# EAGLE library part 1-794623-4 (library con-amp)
MICRO MATE N LOK Dual Row, grid 1.5 mm Source: http://catalog.tycoelectronics.com .. ENG_CD_794623_F.pdf
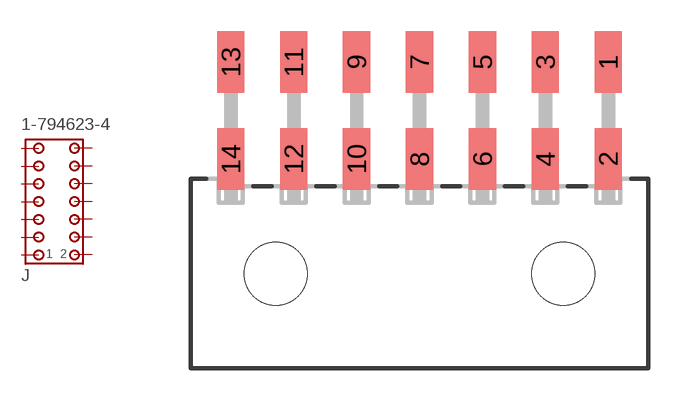
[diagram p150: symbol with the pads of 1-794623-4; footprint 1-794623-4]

Designator prefix J

## 1-794623-4 (MF: TYCO ELECTRONICS; MPN: 1-794623-4; OC_FARNELL: unknown; OC_NEWARK: 10H3684)  [1-794623-4]
1  1  pas
2  2  pas
3  3  pas
4  4  pas
5  5  pas
6  6  pas
7  7  pas
8  8  pas
9  9  pas
10  10  pas
11  11  pas
12  12  pas
13  13  pas
14  14  pas

## Footprint 1-794623-4 (pad centres in mm)
MICRO MATE N LOK Dual Row, grid 1.5 mm Source: http://catalog.tycoelectronics.com .. ENG_CD_794623_F.pdf
smd 1.3 x 2.92: 1 9,10.1; 2 9,5.48; 3 6,10.1; 4 6,5.48; 5 3,10.1; 6 3,5.48; 7 0,10.1; 8 0,5.48; 9 -3,10.1; 10 -3,5.48; 11 -6,10.1; 12 -6,5.48; 13 -9,10.1; 14 -9,5.48
hole 3 at -6.85,0
hole 3 at 6.85,0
